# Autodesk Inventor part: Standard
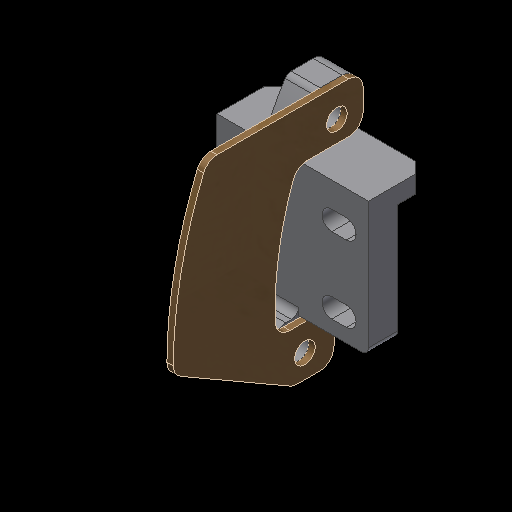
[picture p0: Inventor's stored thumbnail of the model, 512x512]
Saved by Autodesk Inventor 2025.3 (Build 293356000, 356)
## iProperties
RuleStatus: InUse
Created: 2026-05
Project: COMMON
Material: Generic
Catalog Web Link: https://www.janelia.org/
Vendor: HHMI: JRC - JET
Document SubType Name: Modeling
Designer: sohna
Density: 1 g/cm^3
Appearance: Default
AfterDocSave0: file://Part Number Cleaner
LAB/DEPT: COMMON
REQUESTING SCIENTIST: COMMON
DESIGN DEPARTMENT: HHMI: JRC - ID&F
ALTERED ITEM PART NUMBER: N/A
ALTERED ITEM VENDOR: N/A
ALTERED ITEM DESCRIPTION: N/A
Title: Standard
Author: sohna
Revision Number: 0
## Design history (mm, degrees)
sketch "Sketch1"
  geometry: L1 (-9.525, 8.255)-(9.525, 8.255); L2 (9.525, 8.255)-(9.525, -8.255); L3 (9.525, -8.255)-(-9.525, -8.255); L4 (-9.525, -8.255)-(-9.525, 8.255); L5 (-9.525, 8.255)-(9.525, -8.255); L6 (9.525, 8.255)-(-9.525, -8.255); L7 (-11.113, 8.255)-(-7.938, 8.255); L8 (-11.113, 6.13)-(-7.938, 6.13); L9 (-7.938, 10.38)-(-11.113, 10.38); L10 (-17.113, 15.875)-(12.769, 15.875); L11 (12.769, 15.875)-(12.769, -13.335); L12 (12.769, -13.335)-(-17.112, -13.335); L13 (-17.112, -13.335)-(-17.113, 15.875); L14 (0, 21.717)-(0, -19.177) reference; L15 (-23.724, 0)-(22.555, 0) reference; L16 (12.769, 15.875)-(15.944, 15.875); L17 (15.944, 15.875)-(15.944, -13.335); L18 (15.944, -13.335)-(12.769, -13.335); L19 (12.769, -13.335)-(12.769, 15.875); L20 (15.944, 12.065)-(-17.113, 12.065); A1 r 2.125 centre (-11.113, 8.255) between (-11.113, 10.38) and (-11.113, 6.13); A2 r 2.125 centre (-7.938, 8.255) between (-7.938, 6.13) and (-7.938, 10.38); 4 further points
  constraints: 38 end point, 7 parallel, 4 perpendicular, 4 point on circle, 4 point on line, 4 tangent, 3 horizontal, 3 midpoint, 2 centre point, 2 collinear, 1 coincident
  dimensions: "d0" = 16.51 distance of L1.end L2.end; "d1" = 19.05 distance of L2.end L3.end; "d2" = 4.25 distance between parallel lines of L8 L9; "d3" = 3.175 distance of L9.start L9.end; "d4" = 7.62 distance between parallel lines of L10 L1; "d5" = 5.08 distance between parallel lines of L12 L3; "d6" = 6 distance from line of L13 L7.start; "d7" = 3.24358 distance between parallel lines of L11 L2; "d10" = 3.175 distance of L16.start L16.end; "d11" = 3.81 distance between parallel lines of L20 L10
extrude "Extrusion1" new body sketch "Sketch1" distance "d12" = 6.35; taper "d13" = 0 deg
extrude "Extrusion2" join sketch "Sketch1" distance "d14" = 6.35; taper "d15" = 0 deg
extrude "Extrusion3" cut sketch "Sketch1" extent not by distance; stored distance "d16" = 0; taper "d17" = 0 deg
pattern_linear "Rectangular Pattern1" dims "d20" = 19.05, "d23" = 16.51
workaxis "Work Axis1"
workplane "Work Plane1"
sketch "Sketch2"
  geometry: L1 (-13.335, 0)-(12.065, 0) reference; L2 (12.065, 0)-(12.065, -6.35) reference; L3 (15.875, -6.35)-(15.875, 6.35) reference; L4 (8.255, -177.103)-(8.255, 70.423) reference; L5 (-13.335, 0)-(12.065, 0) reference; L6 (12.065, 0)-(12.065, -6.35) reference; L7 (15.875, -6.35)-(12.065, -6.35) reference; L8 (15.875, -6.35)-(15.875, 6.35) reference; L9 (-13.335, 6.35)-(15.875, 6.35) reference; L10 (-13.335, 0)-(-13.335, 6.35) reference; L11 (15.875, 6.35)-(15.875, -6.35); L12 (15.875, 6.35)-(20.32, 6.35); L13 (27.305, 2.471)-(27.305, -6.35); L14 (27.305, -6.35)-(15.875, -6.35); L15 (-13.335, 0)-(-13.335, 12.642); L16 (-13.335, 0)-(-24.765, 0); L17 (-24.765, 0)-(-24.765, 10.745); C1 r 9.525 at (8.255, 21.19); C2 r 88.402 at (-8.255, -53.34); A1 r 66.177 centre (-8.255, -53.34) between (20.32, 6.35) and (27.305, 2.471); A2 r 66.177 centre (-8.255, -53.34) between (27.305, 2.471) and (20.32, 6.35); A3 r 66.177 centre (-8.255, -53.34) between (-13.335, 12.642) and (-24.765, 10.745); 4 further points
  constraints: 14 end point, 8 point on circle, 5 centre point, 3 perpendicular, 2 coincident, 2 concentric, 2 vertical, 1 collinear, 1 horizontal, 1 point on line
  dimensions: "d25" = 53.34 distance from line of point (-8.255, -53.34) L1; "d26" = 20.32 distance from line of point (-8.255, -53.34) L2; "d28" = 19.05 diameter of C1; "d29" = 2.54 dimension on C2 C1; "d30" = 76.33716 distance of point (-8.255, -53.34) C1.centre; "d32" = 0.635 dimension on A1 C1; "d33" = 11.43 distance between parallel lines of L3 L13; "d34" = 11.43 distance between parallel lines of L17 L10; "d35" = 5.08 distance from line of L3 point (20.955, -0.635); "d36" = 5.715 distance from line of L14 point (20.955, -0.635); "d37" = 6.35 distance from line of point (-19.685, 6.35) L15; "d38" = 6.35 distance from line of point (-19.685, 6.35) L16
  node "Projected Loop1"
extrude "Extrusion4" join sketch "Sketch2" distance "d39" = 6.35; taper "d40" = 0 deg
hole "Hole1" sketch "Sketch2" diameter "d41" = 4.4958; stored, may be unused: countersink angle "d45" = 90 deg, drill point angle "d47" = 118 deg; dims "d42" = 19.05, "d43" = 9.398, "d44" = 3.9878, "d46" = 25.4
sketch "Sketch3"
  geometry: L1 (1.386, 17.455)-(-2.656, 17.455); L2 (-2.656, 17.455)-(-4.676, 20.955); L3 (-4.676, 20.955)-(-2.656, 24.455); L4 (-2.656, 24.455)-(1.386, 24.455); L5 (1.386, 24.455)-(3.406, 20.955); L6 (3.406, 20.955)-(1.386, 17.455); L7 (8.371, -23.185)-(4.329, -23.185); L8 (4.329, -23.185)-(2.309, -19.685); L9 (2.309, -19.685)-(4.329, -16.185); L10 (4.329, -16.185)-(8.371, -16.185); L11 (8.371, -16.185)-(10.391, -19.685); L12 (10.391, -19.685)-(8.371, -23.185); C1 r 2.248 at (-0.635, 20.955) reference; C2 r 2.248 at (6.35, -19.685) reference; 3 further points
  constraints: 24 end point, 2 coincident, 2 horizontal, 1 parallel, 26 other
  dimensions: "d48" = 7 distance between parallel lines of L1 L4
extrude "Extrusion5" cut sketch "Sketch3" distance "d49" = 3.2; taper "d50" = 0 deg
sketch "Sketch4"
  geometry: L1 (-6.35, 20.32)-(-6.35, 15.875) reference; L2 (6.35, 15.875)-(-6.35, 15.875) reference; L3 (6.35, 15.875)-(6.35, 27.305) reference; L4 (6.35, 27.305)-(-2.471, 27.305) reference; L5 (-10.745, -24.765)-(0, -24.765) reference; L6 (0, -24.765)-(0, -13.335) reference; L7 (-6.35, -13.335)-(0, -13.335) reference; L8 (-6.35, -13.335)-(-12.642, -13.335) reference; L9 (0, -13.843)-(-12.601, -13.843); L10 (6.35, 16.383)-(-8.08, 16.383); L11 (-2.471, 27.305)-(-27.595, 27.305); L12 (-10.745, -24.765)-(-33.507, -24.765); L13 (-10.745, -24.765)-(0, -24.765) reference; L14 (-8.89, -24.765)-(-35.051, -9.661); C1 r 2.248 at (0.635, 20.955) reference; C2 r 2.248 at (-6.35, -19.685) reference; C3 r 9.525 at (-21.19, 8.255) reference; A1 r 66.177 centre (53.34, -8.255) between (-2.471, 27.305) and (-6.35, 20.32) reference; A2 r 66.177 centre (53.34, -8.255) between (-12.642, -13.335) and (-10.745, -24.765) reference; A3 r 66.177 centre (53.34, -8.255) between (-6.35, 20.32) and (-2.471, 27.305) reference; A4 r 88.402 centre (53.34, -8.255) between (-27.595, 27.305) and (-33.507, -24.765) reference; A5 r 66.177 centre (53.34, -8.255) between (-8.08, 16.383) and (-12.601, -13.843); A6 r 88.402 centre (53.34, -8.255) between (-27.595, 27.305) and (-33.507, -24.765); 4 further points
  constraints: 10 end point, 9 point on circle, 3 horizontal, 3 point on line, 2 centre point, 2 concentric, 1 parallel
  dimensions: "d51" = 0.508 distance between parallel lines of L9 L7; "d52" = 0.508 distance between parallel lines of L2 L10; "d61" = 8.89 distance from line of L6 L14.start; "d62" = 30 deg angle of L12 L14
extrude "Extrusion6" new body sketch "Sketch4" distance "d53" = 1.397; taper "d54" = 0 deg
fillet "Fillet1" dims "d55" = 1.524
fillet "Fillet2" dims "d56" = 3.175
chamfer "Chamfer1" distance "d57" = 2.54; stored, may be unused: second distance "d58" = 3.175, angle "d59" = 45 deg
fillet "Fillet3" dims "d60" = 3.175
body "Solid1"
node "Projected Loop2"
node "Projected Loop3"
body "Solid2"
other parameters: "d24" = 0.6858
